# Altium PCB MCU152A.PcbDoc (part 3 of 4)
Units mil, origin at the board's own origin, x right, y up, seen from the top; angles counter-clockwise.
Board outline 2307.9 x 3007.9 mil, 4 copper layers (Top Signal, GND, PWR, Bottom Signal), stack 61.6 mil thick; 198 components, 136 nets, 740 pads, 401 vias.
Unrouted connection lines stored in the file: 147.
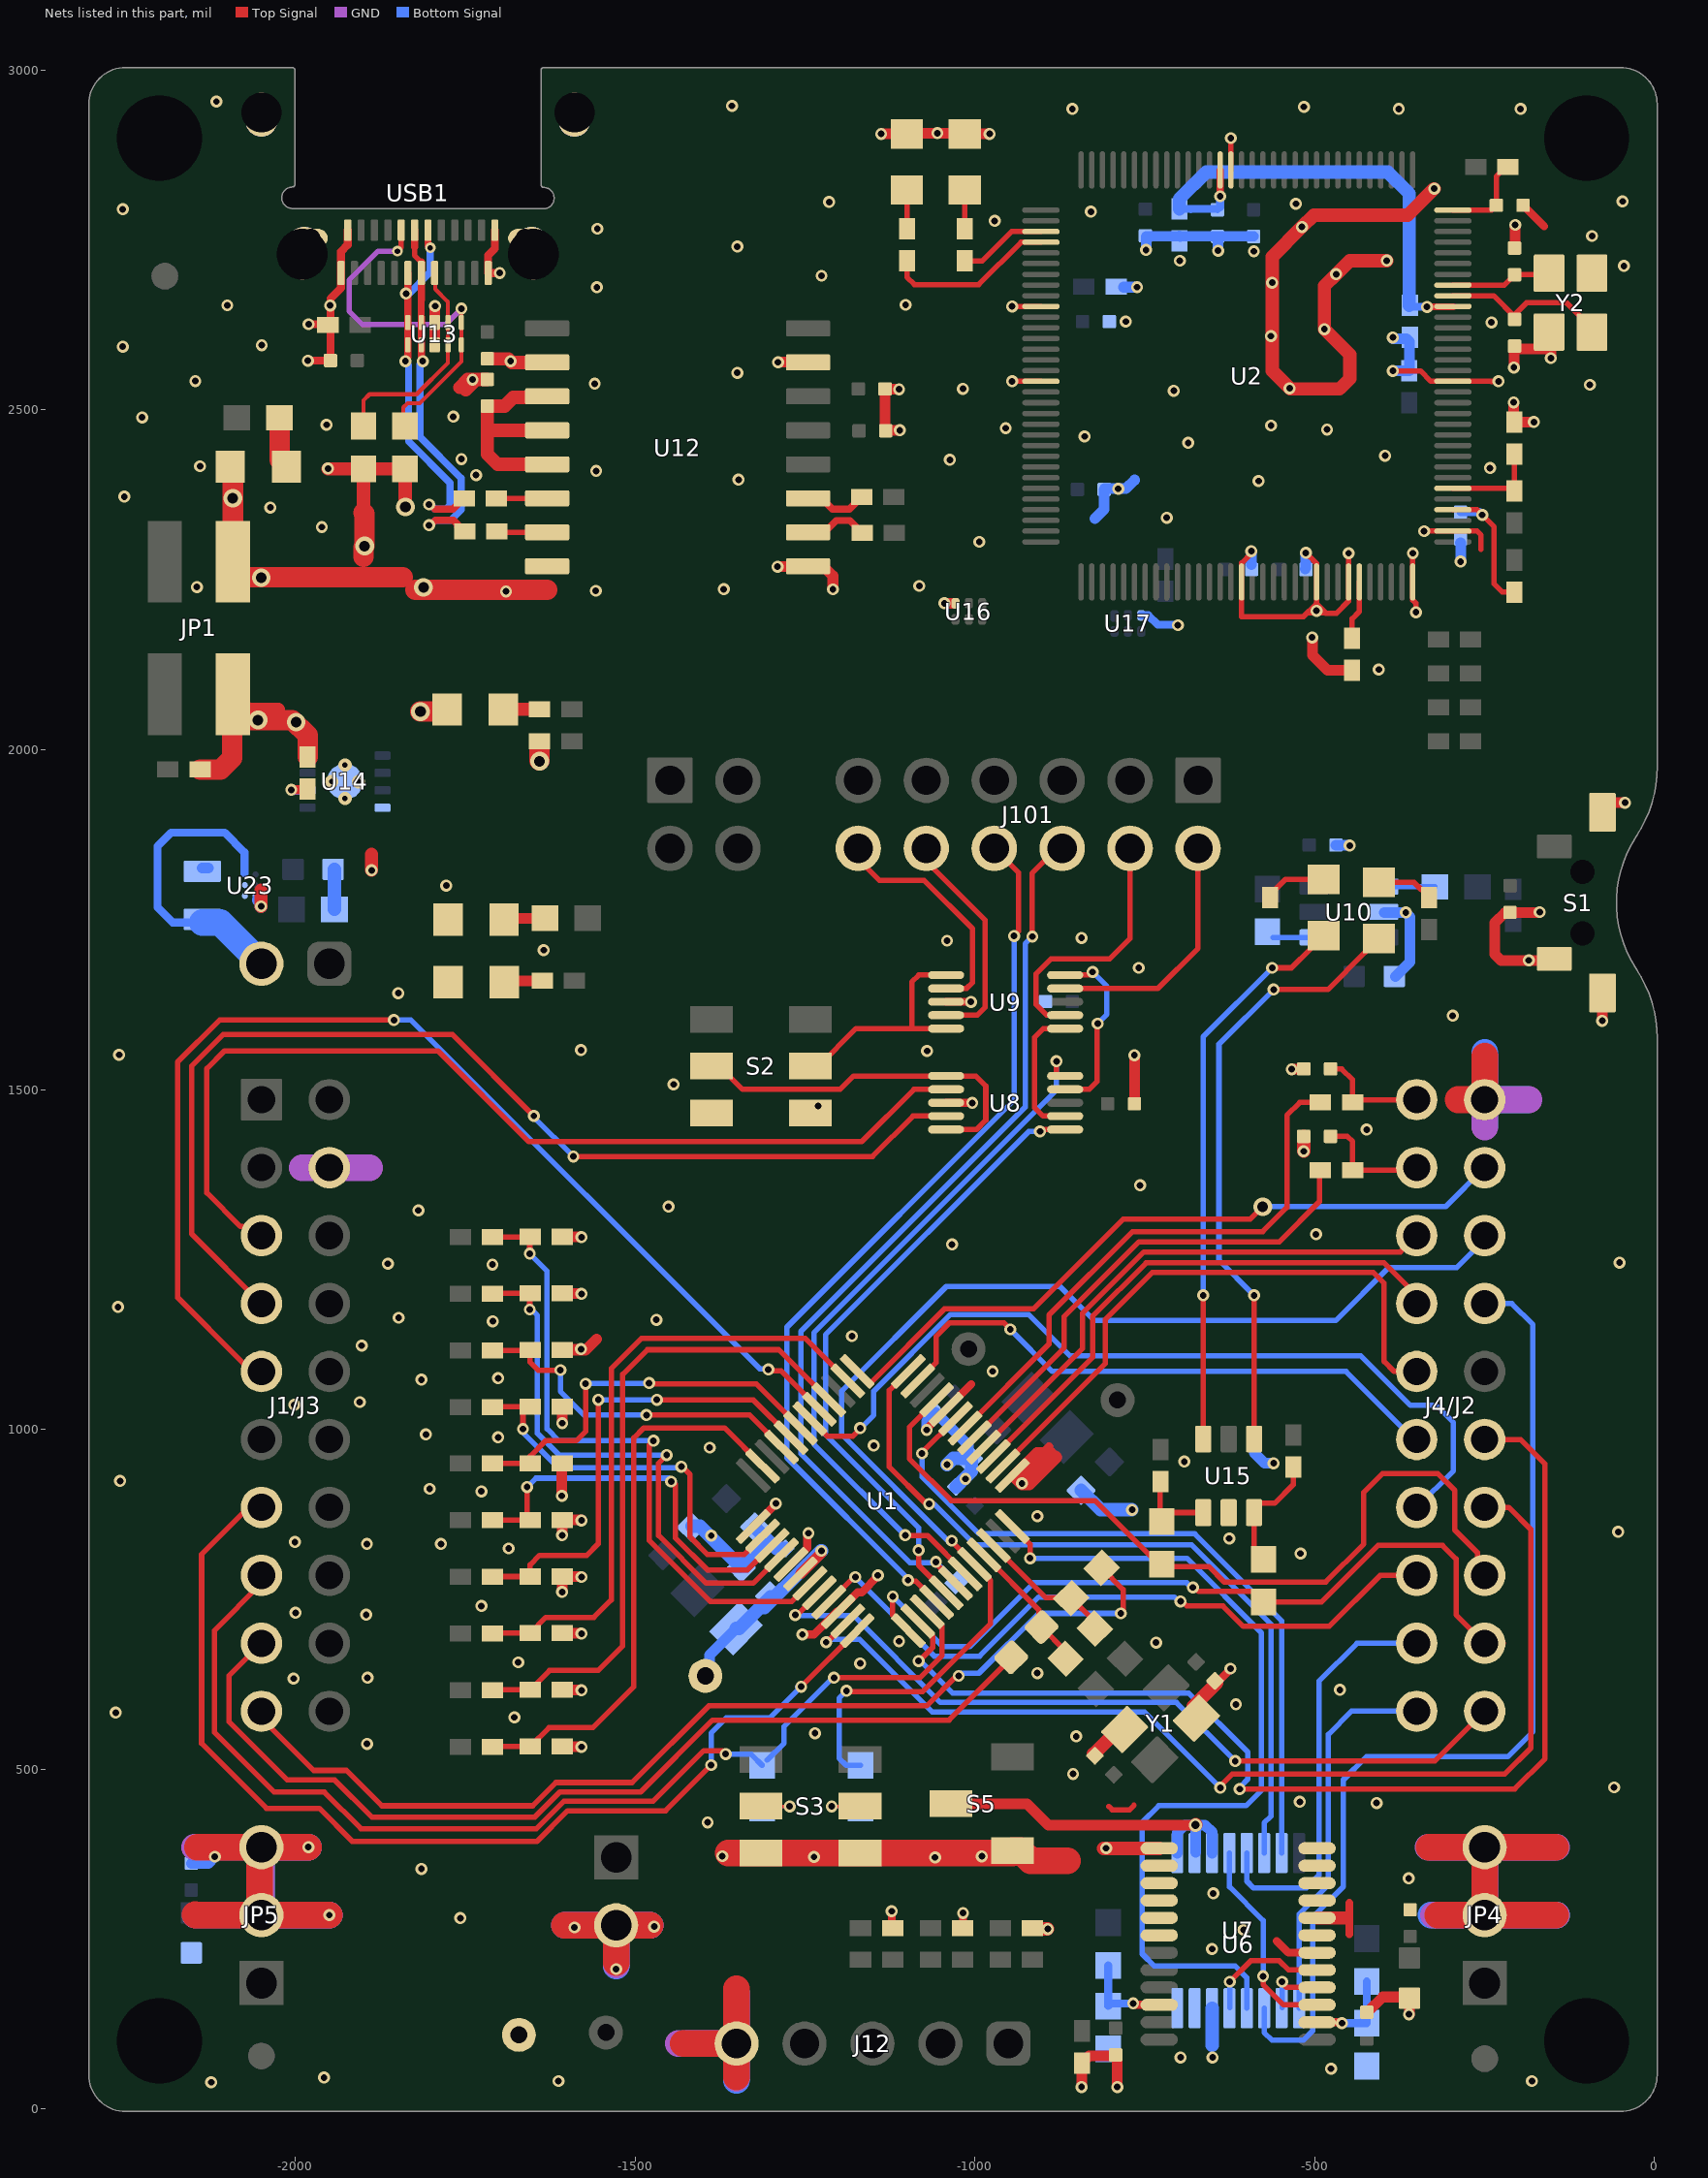
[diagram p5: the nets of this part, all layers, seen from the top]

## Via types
v1: diameter 17.72, hole 9.84, Top Signal to Bottom Signal, tented both sides, 368 vias
v2: diameter 27.56, hole 15.75, Top Signal to Bottom Signal, tented both sides, 21 vias
v3: diameter 19.68, hole 11.81, Top Signal to Bottom Signal, tented both sides, 6 vias
v4: diameter 19.68, hole 7.87, Top Signal to Bottom Signal, tented both sides, 4 vias
v5: diameter 15.75, hole 7.87, Top Signal to Bottom Signal, tented both sides, 2 vias

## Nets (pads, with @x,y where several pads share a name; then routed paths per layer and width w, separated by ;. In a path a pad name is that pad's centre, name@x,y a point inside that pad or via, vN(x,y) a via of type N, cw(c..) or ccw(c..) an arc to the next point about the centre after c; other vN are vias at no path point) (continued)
GND: C1.1 C2.1 C3.2 C4.2 C5.1 C6.2 C7.2 C8.2 C9.2 C10.2 C11.1 C12.2 C13.2 C14.2 C15.2 C17.2 C18.2 C19.2 C20.2 C21.2 C22.2 C23.2 C28.2 C29.2 C30.2 C31.1 C32.1 C34.2 C35.2 C36.2 C37.1 C38.1 C43.2 C45.2 C58.1 C59.1 C62.2 C63.2 C64.2 C65.1 C66.1 C67.1 C68.1 C69.1 C70.1 C71.2 C72.2 C73.1 C74.2 C75.1 C76.2 C77.1 C78.2 C79.2 C80.2 C81.2 C119.2 C120.2 C124.2 C125.1 J1/J3.22 J4/J2.20 J12.5 J15.2 JP1.4 JP4.2 JP4.3 JP5.2 JP5.3 LED0.1 LED1.1 LED2.1 LED3.1 LED6.1 R18.1 R19.2 R75.1 R76.1 S1.1 S1.2 S1.3 S2.3 S2.6 S3.1 S3.4 S5.1 TP6.1 U1.13 U1.17 U1.22 U1.37 U1.44 U2.10 U2.17 U2.48 U2.55 U2.58 U2.64 U2.66 U2.80 U2.114 U6.6 U6.7 U6.8 U6.9 U6.10 U6.11 U6.12 U6.13 U6.14 U6.15 U6.16 U6.17 U6.18 U7.6 U7.7 U7.8 U8.3 U9.3 U10.2 U12.9 U12.15 U14.4 U14.9 U15.2 U16.3 U17.3 U23.A2 Y1.2 Y1.4 Y2.2 Y2.4 | length 11507.1
  Top Signal w7.87: v1(-945.31,2542.13) U2.17@-902.95,2542.13 ; v1(-945.31,2652.36) U2.10@-902.95,2652.36 ; -803,445 -798.11,440.11 -772.47,440.11 -766,446.58 ; U2.114@-623.43,2853.15 v1(-623.43,2900) ; v1(-593.35,2292.32) -593.35,2289.14 -607.68,2274.81 U2.48@-607.68,2246.85 -607.68,2196 -516.51,2196 -497.79,2214.72 ; v1(-513.11,2289.8) -513.11,2289.61 -507.76,2284.25 -507.48,2284.25 -497.44,2274.21 U2.55@-497.44,2246.85 v1(-497.44,2204.49) ; -508.79,2201.72 -486.45,2201.72 ; -497.09,2214.72 -483.37,2201 -467.81,2201 -450.2,2218.62 U2.58@-450.2,2246.85 v1(-450.2,2289.21) ; v1(-385,2557.48) -344.54,2557.48 -329.19,2542.13 U2.80@-296.65,2542.13 -240.1,2542.13 -239.8,2541.83 ; v1(-355.71,2289.21) U2.64@-355.71,2246.85 -355.71,2220.32 -351.02,2215.63 v1(-351.02,2202.32) ; v1(-339.02,2321.65) U2.66@-296.65,2321.65 -261.09,2321.65 -255.18,2315.74 -255.18,2295
  Top Signal w11.81: U1.13@-1326.37,856.84 v1@-1292.68,890.53 ; U1.17@-1270.69,801.17 -1246.67,825.18 -1246.67,845.33 v1(-1245,847) ; v1(-1254,698) -1236.78,698 -1203.22,731.57 U1.22@-1201.09,731.57 -1172.66,760 -1166.57,760 v1@-1142.25,784.32 ; C20.2@-1122.47,267.36 v1(-1122.47,290.68) ; v1(-1071,999) -1071,1000.85 U1.44@-1042.41,1029.44 -1005.53,1066.32 ; U8.3@-1042.51,1480.5 v1@-1004.25,1480.5 ; U9.3@-1042.51,1629 v1(-1006,1629) ; C19.2@-1017.55,266.57 v1(-1017.55,288.19) ; v1@-927.92,926.97 -892.02,962.87 ; -891,974.61 -897.7,967.91 ; -887,967.91 -897.7,967.91 ; C4.2@-644.05,626.87 -623.99,646.92 v1(-623.99,647.76) ; -555.93,247 -538.64,229.7 U6.6@-496.61,229.7 ; -449,257 -449,302.92 ; C65.1@-192.44,2800.24 -162.28,2770.08 ; -897.7,967.91 -909.07,967.91 U1.37@-944.97,932.01 -933.6,932.01 -897.7,967.91
  Top Signal w15.75: v1(-1608,902) -1608,947.25 -1607,948.25 C13.2@-1608,949.25 ; v1(-1607.5,843.96) -1607.38,844.08 C8.2@-1607.38,866.54 v1@-1579,866.54 ; C15.2@-1607.38,533.21 v1@-1579,533.21 ; C23.2@-1607.38,616.54 v1@-1579,616.54 ; C14.2@-1607.38,699.88 v1@-1579,699.88 ; v1@-1607.38,760.74 C9.2@-1607.38,783.21 v1@-1579,783.21 ; v1(-1607.38,1009) C22.2@-1607.38,1033.21 ; C21.2@-1607.38,1199.88 v1@-1579,1199.88 ; C7.2@-1607.38,1283.21 v1@-1579,1283.21 ; v1(-1579.77,1118) -1605.92,1118 C17.2@-1607.38,1116.54 -1572.87,1116.54 -1556.42,1133 ; v1(-1290.55,2269.29) U12.9@-1270.71,2269.29 ; v1(-1289.76,2570.24) U12.15@-1244.41,2570.24 ; U12.9@-1222.68,2269.45 -1209.11,2255.89 -1209,2256 v1(-1209,2236) ; v1(-1138.11,2906.38) LED3.1@-1118.27,2906.38 ; C59.1@-1132.31,2470.39 C58.1@-1132.31,2531 ; C59.1@-1132.05,2470.12 C59.1@-1131.3,2469.37 ; C58.1@-1132.05,2530.45 v1(-1111.68,2530.45) ; C59.1@-1130.51,2470.08 v1(-1110.67,2470.08) ; LED3.1@-1090.2,2907.24 v1(-1055.28,2907.24) LED2.1@-1035.43,2907.24 ; v1@-1044.91,2215.54 U16.3@-1032,2215.54 ; LED2.1@-998.39,2906.18 v1(-978.54,2906.18) ; v1(-843.12,32) C12.2@-843.12,66.45 ; C12.2@-842.19,67.38 -831.91,77.66 -794.65,77.66 C11.1@-793,79.32 ; v1(-790.5,32) C11.1@-790.5,76.82 ; C45.2@-765.32,1479 v1@-765.32,1550.5 ; v1(-533.93,1529.82) -533.49,1530.25 C2.1@-516.21,1530.25 ; v1@-503,2165 -503,2139 -480.93,2116.93 R76.1@-445,2116.93 ; C10.2@-422.59,142.04 -422.59,142.95 -421.53,144.01 -420.63,144.01 -400.14,164.49 -360.68,164.49 v1@-360.68,138.97 ; R75.1@-207.32,2491.34 v1(-207.32,2511.18) ; v1(-206.93,2562.6) -206.93,2582.44 ; C79.2@-205.98,2590 Y2.4@-158.74,2590 ; C78.2@-205.98,2738.31 -205.34,2738.95 -205.34,2772.03 v1(-204.96,2772.4) -204.96,2752.56 ; R75.1@-197.32,2482.24 v1(-177.48,2482.24) ; v1@-168.6,1760.6 C38.1@-212.72,1760.6 -219.81,1760.6 -235.17,1745.25 -235.17,1699.1 -226.1,1690.02 v1(-185,1690.02) -149.86,1690.02 S1.3@-147.56,1692.32 ; v1(-152.64,2576.26) Y2.4@-152.64,2596.1 ; v1(-77,1601) S1.1@-77,1641.82 ; S1.2@-62.57,1922 v1(-43.5,1922)
  Top Signal w19.68: JP1.4@-2076.12,2043.64 -2093,2060.53 -2103,2070.53 JP1.4@-2091.97,2081.56 -2069.47,2059.06 -2025.47,2059.06 ; v1(-2050.5,1769.62) -2050.5,1793.11 ; v1(-1887.89,1822.62) -1887.89,1846.11 ; U1.37@-941.25,930.62 v1(-930.91,920.27) -920.27,920.27 -882,958.54 ; C18.2@-914,264.62 v1(-893,264.62) ; C3.2@-826.07,522.34 -824.85,522.34 -789.06,558.13 Y1.4@-779.89,558.13 ; v1@-810.58,383.25 U6.13@-728.89,383.25 ; Y1.2@-678.75,592.16 C4.2@-644.05,626.87 ; v1(-516.32,1409) C1.1@-516.32,1430.89 ; U6.8@-496.61,280.89 -454,280.89 ; v1(-394.09,2719.68) -448.58,2719.68 v1(-468.5,2699.76) -485.83,2682.44 v1(-485.83,2618.8) -448.58,2581.56 -448.58,2545.92 -463.59,2530.91 -536.02,2530.91 v1(-537.01,2531.89) -562.6,2557.48 v1(-562.6,2687.4) -562.6,2725.43 v1(-518.74,2769.29) -501.42,2786.61 -363.19,2786.61 v1(-324.21,2825.59) ; Y2.2@-95,2704.09 Y2.2@-92.13,2701.22 Y2.2@-91.91,2701
  Top Signal w30: C62.2@-2140.38,1971 -2110,1971 -2093,1988 -2093,2060.53 JP1.4@-2093,2071 ; JP1.4@-2080.59,2043.64 -2076.12,2043.64 v2(-2055,2043.64) -2004.64,2043.64 -1982.12,2021.12 C63.2@-1982.12,1989.42 ; v2(-1816,2056) LED0.1@-1780.21,2056 ; v2@-1640.59,1984.25 C64.2@-1640.59,2007
  Top Signal w39.37: -2147.75,285.56 -2147.19,285 JP5.2@-2053,285 ; -2143.75,385 -2053,385 JP5.2@-2053,285 ; JP5.2@-2053,276.18 JP5.2@-2053,285 ; JP5.3@-2050,385 v1(-1981,385) ; v1(-1950,285) JP5.2@-2050,285 JP5.2@-2053,285 ; -1604,270 J15.2@-1528,270 ; -1528,215 J15.2@-1528,270 ; v1@-1478,270 J15.2@-1528,270 ; -1429.02,95.98 J12.5@-1350.8,95.98 ; -1350.8,46.78 J12.5@-1350.8,95.98 ; -1350.8,176.67 J12.5@-1350.8,95.98 ; S3.4@-1314.87,376.25 -1363,376.25 ; v1@-1236.85,376.25 -1363,376.25 ; S5.1@-944.72,376.25 -1363,376.25 ; S5.1@-944.72,380.1 -932.91,380.1 -918.01,365.2 -864.16,365.2 ; -332,385 JP4.3@-250,385 ; -319,285 JP4.2@-250,285 ; -289.23,1485 J4/J2.20@-250,1485 -250,1549 ; -146,285 JP4.2@-250,285 ; -146,385 JP4.3@-250,385 ; JP4.2@-250,285 JP4.3@-250,385
  GND w39.37: -2148.25,385.06 -2148.19,385 JP5.3@-2050,385 ; -2147.25,285.06 -2147.19,285 JP5.2@-2050,285 ; -1989.76,1385 J1/J3.22@-1950,1385 -1891,1385 ; v1(-1981,385) JP5.3@-2050,385 ; v1(-1950,285) JP5.2@-2050,285 ; -1602,270 J15.2@-1528,270 ; v1@-1528,211.56 J15.2@-1528,270 ; v1@-1478,270 J15.2@-1528,270 ; -1436.68,95.98 J12.5@-1350.8,95.98 ; -1350.8,44.8 J12.5@-1350.8,95.98 ; -1350.8,168.7 J12.5@-1350.8,95.98 ; -333,385 JP4.3@-250,385 ; -325,285 JP4.2@-250,285 ; -250,1444.77 J4/J2.20@-250,1485 ; -250,1549.19 J4/J2.20@-250,1485 ; -185,1485 J4/J2.20@-250,1485 ; -144,285 JP4.2@-250,285 ; -144,385 JP4.3@-250,385 ; JP5.2@-2050,285 JP5.3@-2050,385 ; JP4.2@-250,285 JP4.3@-250,385
  Bottom Signal w11.81: U17.3@-755.32,2197.81 -744.81,2197.81 -731,2184 v1@-701.67,2184
  Bottom Signal w15: C67.1@-748.23,2755.24 -747.7,2755.77 -698.72,2755.77 -590.45,2755.77 C66.1@-590,2755.32
  Bottom Signal w15.75: C81.2@-2153.25,361.25 -2128.25,361.25 v1(-2118.5,371) ; v1(-1071,999) -1071,1012 C32.1@-1057.92,1025.08 -1009.61,976.77 C30.2@-1009.61,957.12 ; -823.23,2340.16 -809.88,2353.5 C70.1@-809.88,2383.11 ; C70.1@-808.9,2384.09 v1(-789.05,2384.09) -778.11,2384.09 -765.35,2396.85 ; C72.2@-781.38,2680.75 v1(-761.54,2680.75) ; v1(-748.23,2735.39) C67.1@-748.23,2755.24 ; C76.2@-699.17,2756.22 -698.72,2755.77 C76.2@-698.04,2755.09 ; v1(-642.17,2734.41) C75.1@-642.17,2754.25 ; C69.1@-593.35,2272.48 v1(-593.35,2292.32) ; C5.1@-588.58,981.45 -588.58,965 -573.61,950.03 v1(-560.5,950.03) ; C68.1@-514.02,2266.26 -513.11,2267.17 v1(-513.11,2289.8) ; C124.2@-468.77,1859.72 v1@-449.3,1859.72 ; U10.2@-397.74,1760.6 v1(-366,1760.6) -366,1760.07 -359.96,1754.03 -359.96,1687.54 C125.1@-381.06,1666.45 ; v1(-385,2557.48) C71.2@-365.16,2557.48 ; v1@-385,2604.76 -365.16,2604.76 -360.79,2600.39 C71.2@-360.79,2557.76 ; C77.1@-285.47,2304.76 -285.39,2304.68 v1(-285.39,2276.86)
  Bottom Signal w19.68: -2053.8,1778.92 -2050.5,1775.62 v1(-2050.5,1769.62) ; C119.2@-1942.5,1765 C120.2@-1942.5,1824 ; C35.2@-1416.05,857.27 -1404.71,857.27 -1345.18,797.75 -1307.6,835.34 ; C6.2@-1322.62,854.73 -1292.46,824.57 C37.1@-1278.81,824.57 ; v1(-1041,948) -1031.88,957.12 C30.2@-1009.61,957.12 ; C31.1@-1027.92,915.26 -1005,938.18 C30.2@-1005,954 ; C29.2@-843.88,910.12 -815.24,881.48 v1(-768.83,881.48) ; -651.14,93.38 U7.6@-651.14,148.01
  Bottom Signal w39.37: v1(-1981,385) JP5.3@-2050,385 JP5.2@-2050,285 v1(-1950,285) ; -1604,270 J15.2@-1528,270 ; v1@-1528,210.06 J15.2@-1528,270 ; v1@-1478,270 J15.2@-1528,270 ; -1422.11,95.98 J12.5@-1350.8,95.98 ; -1350.8,42.2 J12.5@-1350.8,95.98 ; -1350.8,171.05 J12.5@-1350.8,95.98 ; -328.85,285 JP4.2@-250,285 ; -328.85,385 JP4.3@-250,385 ; -250,1446.84 J4/J2.20@-250,1485 ; -250,1554.26 J4/J2.20@-250,1485 ; -187.75,1485 J4/J2.20@-250,1485 ; -148.5,385 JP4.3@-250,385 ; -144,285 JP4.2@-250,285 ; JP4.2@-250,285 JP4.3@-250,385
  other v1: -2124,39 -1613,40.74 -180.5,40.74 -1957.94,46 -476.1,59 -697.5,75.54 -650.47,75.54 -361.41,138.97 -1527.99,205.56 -651.18,235.06 -604.7,263.32 -1589.37,266.85 -1472,268 -1757.36,280.5 -649.37,317 -361.7,338.97 -1814.6,353 -1058.8,369.93 -1236.85,370.67 -1371.85,371.67 -990,371.5 -807,383.5 -1393.42,421.5 -409.07,450 -521.94,451.82 -59.5,473 -855.68,492.82 -1579,532.53 -1894.69,536.97 -851,548.03 -1235.46,552.59 -1677.69,575.97 -2264.5,583 -616,595 -1579,615.86 -462.94,616.5 -2002.69,633.15 -1893.89,634.31 -908.27,641.07 -1169,655.38 -1672.2,656.97 -733.49,686.11 -1111.68,688 -1579,699.2 -1895.89,727.03 -1999.69,729.97 -1726.26,739.87 -1607.5,760.62 -1579,782.53 -1142.86,784.93 -521,817.16 -1686.21,824.61 -1894.78,831.09 -1785.94,831.09 -2000.69,833.97 -625.71,839.19 -1388,843.47 -53.48,849 -1579,865.86 -908.27,872 -1293,890.85 -1726.31,908.54 -1802.47,912.32 -2258,924 -1014,927 -692,952.53 -1390.33,972.93 -1149,976 -1701.61,988 -1808,992.3 -2001.69,1035.97 -1905.21,1039.97 -1814.6,1073.02 -1701.61,1075.15 -974,1085.26 -1902.5,1123 -1181,1137 -1709.59,1158.96 -1468.92,1160.94 -1848,1164.1 -2261,1180 -1579,1199.2 -1710.01,1242.31 -1863.89,1243.62 -51.5,1245.17 -1033.85,1272 -1579,1282.53 -498.03,1287 -1818.94,1322 -1451,1327.5 -757,1359 -423.7,1441.06 -1231,1476 -1004,1480.25 -1443.41,1507.5 -2259.5,1551 -765.35,1550.5 -1070.5,1556.72 -1579.77,1558 -297,1608.52 -1848.66,1641.85 -758.94,1679.04 -1634.72,1705 -1041.02,1718.94 -843.14,1723 -169,1761 -1777.94,1800.11 -448.58,1859 -405.66,2117.97 -503.93,2165.32 -701.37,2183.32 -1045,2215.63 -1369.76,2236.22 -1082,2241 -993.7,2305.91 -717.91,2341.5 -582.6,2395.43 -1347.87,2397.4 -242.14,2414.51 -1037.01,2426.73 -396.46,2432.68 -686.22,2451.57 -838.58,2461.02 -481.89,2471.26 -954.72,2473.23 -564.29,2477.05 -707.48,2528.35 -1017.76,2531.22 -95.26,2537 -229.61,2542.13 -1349.8,2554.57 -385,2606.65 -564.57,2608.62 -239.96,2628.74 -777.95,2630.05 -1102,2654.68 -1225.79,2697.52 -45,2712 -698.52,2719.56 -589.56,2733.48 -1349.8,2740.51 -92,2756 -971.06,2778.35 -829.41,2791.81 -527.83,2803.35 -1214.49,2806.11 -47,2807 -856.77,2942.99 -376.38,2942.99 -197.09,2942.99 -516,2946 -1357.48,2947.52
  other v2: -1640.59,1983 -1999,2040.64
  other v4: -1927,1928.39 -1946.68,1953 -1907.32,1953 -1927,1977.61
GPIO0: R1.1 U1.42 | length 826
  Top Signal w7.87: U1.42@-1014.57,1001.6 -891,1125.18 -891,1168 -768,1291 -576.5,1291 -541,1326.5 -541,1462 -522,1481 R1.1@-491.62,1481
GPIO1: R2.1 U1.41 | length 725.2
  Top Signal w7.87: U1.41@-1000.65,987.69 -869,1119.34 -869,1165.61 -758.61,1276 -551.91,1276 -493,1334.91 -493,1379.62 R2.1@-491.62,1381
GPIO2: J4/J2.38 U1.40 | length 796.1
  Top Signal w7.87: U1.40@-986.73,973.77 -841.48,1119.02 -841.48,1171 -751.49,1261 -374,1261 J4/J2.38@-350,1285
GPIO3: J4/J2.37 U1.39 | length 808
  Top Signal w7.87: U1.39@-972.81,959.85 -827,1105.66 -827,1166 -748.22,1244.78 -397.78,1244.78 -350,1197 J4/J2.37@-350,1185
GPIO4: J4/J2.36 U1.38 | length 892.9
  Top Signal w7.87: U1.38@-958.89,945.93 -808,1096.82 -808,1161.75 -738.75,1231 -414,1231 -398,1215 -398,1099.89 -383.11,1085 J4/J2.36@-350,1085
GPIO5: J4/J2.35 U1.47 | length 863.5
  Top Signal w7.87: U1.47@-1084.17,1071.2 -1057,1098.37 -1057,1136.81 -1037.12,1156.69 -957.53,1156.69 -950.74,1149.89 v1@-946.47,1149.89
  Bottom Signal w7.87: v1(-948,1147) -886,1085 -454,1085 -354,985 J4/J2.35@-350,985
GPIO6: U1.48 U7.14 | length 1154.7
  Top Signal w7.87: U1.48@-1098.09,1085.12 -1126,1057.21 -1126,944.51 -1073.49,892 v1@-1063,892
  Bottom Signal w7.87: v1(-1067.5,890) -1062,890 -1061.15,890.85 -1000.43,830.14 -681.45,830.14 -564.57,713.25 -564.57,430.43 -574.36,420.64 U7.14@-574.36,376.36
GPIO6_BP: J4/J2.32 U7.13 | length 611.9
  Bottom Signal w7.87: U7.13@-599.96,376.36 -599.96,334.96 -590,325 -512.44,325 -493.78,343.66 -493.78,629.22 -438,685 J4/J2.32@-350,685
GPIO6_Q1A: U6.3 U7.12 | length 305.7
  Top Signal w7.87: v1(-576,195) -576,183 -545.93,152.93 U6.3@-496.61,152.93
  Bottom Signal w7.87: U7.12@-625.55,376.36 -625.55,326.55 -576,277 v1(-576,195)
GPIO7: U1.43 U7.15 | length 1064.7
  Top Signal w7.87: v1(-1077.87,964.41) -1077.87,965.68 -1028.49,1015.06 U1.43@-1028.49,1015.52
  Bottom Signal w7.87: v1(-1077.87,964.41) -1077.87,929.87 -994,846 -676.62,846 -548.77,718.16 U7.15@-548.77,376.36
GPIO7_BP: J4/J2.31 U7.1 | length 565
  Bottom Signal w7.87: U7.1@-523.18,148.01 -523.18,286.38 -480,329.56 -480,551 -446,585 J4/J2.31@-350,585
GPIO7_Q1B: U6.4 U7.2 | length 95.4
  Top Signal w7.87: v1(-548,187) -548,185 -541.52,178.52 U6.4@-496.61,178.52
  Bottom Signal w5: U7.2@-548.77,148.01 U7.2@-548,148.79
  Bottom Signal w7.87: U7.2@-548,148.79 v1(-548,187)
GPIO12: J1/J3.7 U1.24 | length 1580.6
  Top Signal w7.87: J1/J3.7@-2050,885 -2069,885 -2138,816 -2138,537.56 -2042.44,442 -1964.75,442 -1916.19,393.44 -1644.5,393.44 -1599.4,438.54 -1455.43,438.54 v1(-1388.21,505.76) ; v1(-1255.75,621.24) U1.24@-1173.25,703.73
  Bottom Signal w7.87: v1(-1388.21,505.76) -1388.21,552.79 -1366,575 -1301.98,575 v1(-1255.75,621.24) v1@-1260.76,621.24
GPIO13: J4/J2.14 U1.23 | length 1605.8
  Top Signal w7.87: v1(-1219,686.55) -1215.37,686.55 -1216.82,688 U1.23@-1187.17,717.65 ; v1(-639,472.37) -639,475 -621.18,492.82 -220.18,492.82 -182,531 -182,852.5 -214.5,885 J4/J2.14@-250,885
  Bottom Signal w7.87: v1(-1219,686.55) -1214.55,691 -1169.98,691 -1062.98,584 -750.63,584 v1(-639,472.37)
GPIO16: J4/J2.15 U1.26 | length 1683.4
  Top Signal w7.87: U1.26@-1084.17,717.65 -1062.28,695.76 -1062.28,678.72 -1082.95,658.05 -1083,658.09 v1(-1083,659) ; v1(-610.56,470.52) -205.84,470.52 -161,515.35 -161,948.88 -197.12,985 J4/J2.15@-250,985
  Bottom Signal w7.87: v1(-1083,659) -1080,659 -1033,612 -685.6,612 -598.3,524.7 -598.3,485.44 -610.56,473.18 v1(-610.56,470.52)
GPIO18_BP: J1/J3.9 R12.1 | length 1442
  Top Signal w8: J1/J3.9@-2050,685 -2097.5,637.5 -2097.5,569.5 -2011.92,483.92 -1942.19,483.92 -1887.56,429.29 -1647.72,429.29 -1610.84,466.16 -1491.84,466.16 -1386,572 -1038,572 -946.56,663.44 R12.1@-946.56,664.28
GPIO18_X2: R10.1 R12.2 U1.33 | length 181.5
  Top Signal w8: U1.33@-986.73,815.08 -906.02,734.37 R12.2@-906.02,717 ; R12.2@-902.02,708.83 R10.1@-866.65,673.45
GPIO19_BP: J1/J3.10 R13.1 | length 1523.7
  Top Signal w8: J1/J3.10@-2050,585 -2050,575 -1973,498 -1924.84,498 -1872.67,445.83 -1650.84,445.83 -1616.6,480.07 -1504.58,480.07 -1391.63,593.02 -1070.99,593.02 v1@-1025.01,639.01 ; R13.1@-813.79,796.01 -781.93,764.14 v1@-781.93,728
  Bottom Signal w8: v1@-1023,641 -994.32,641 -906.32,729 v1(-785.43,729)
  other v1: -1024,637
GPIO19_X1: R11.1 R13.2 U1.34 | length 190.7
  Top Signal w8: U1.34@-972.81,829 -895.81,752 R13.2@-863.04,752 ; R13.2@-858.34,751.47 R11.1@-823.63,716.76
GPIO24: J1/J3.8 R15.1 U1.27 | length 1592.4
  Top Signal w7.87: J1/J3.8@-2050,785 -2050,773 -2119,704 -2119,553.69 -2031.25,465.94 -1957.3,465.94 -1903.51,412.16 -1645.27,412.16 -1605.11,452.32 -1473.68,452.32 -1399,527 -1371.74,527 v1(-1366.85,522.11) ; v1@-1209.29,634.31 v1(-1207.5,634.31) -1081.24,634.31 -1048.5,667.05 -1048.5,709.82 U1.27@-1070.25,731.57
  Bottom Signal w7.87: v1@-1364.85,520.11 v1(-1366.85,522.11) R15.1@-1329.85,522.11 ; R15.1@-1327.85,520.11 -1313.17,505.43 R15.1@-1313.08,505.43 R15.1@-1313.08,505.89 ; R15.1@-1306,513 -1281,538 -1281,562.6 -1209.29,634.31 v1(-1207.5,634.31)
GPIO29: J4/J2.19 U1.1 | length 1060.4
  Top Signal w7.87: U1.1@-1173.25,1085.12 -1157.59,1069.46 -1152.54,1069.46 -1045,1177 -913.93,1177 -781.93,1309 -595,1309 v2(-576.5,1327.5)
  Bottom Signal w7.87: v2(-576.5,1327.5) -307.5,1327.5 J4/J2.19@-250,1385
GPIO32: J4/J2.18 R16.2 U1.32 | length 1917.5
  Top Signal w7.87: v1@-1189,614 -1077,614 -977,714 -977,777.51 U1.32@-1000.65,801.17 -1035.49,836 v1(-1034,836)
  Bottom Signal w7.87: v1(-1189,615) -1200,604 -1200,516 -1189.43,505.43 R16.2@-1168.35,505.43 ; v1(-1034,836) -1040,836 -1196,992 -1196,1056.23 -1042.15,1210.08 -874.7,1210.08 -824.44,1159.83 -469.17,1159.83 -391,1238 -291,1238 -250,1279 J4/J2.18@-250,1285
GPIO33: J4/J2.12 R9.1 U1.25 | length 1192.1
  Top Signal w7.87: v1(-1121,753.9) -1121,726.64 U1.25@-1098.09,703.73 ; v1(-679.29,767.24) -676.63,767.24 -670.61,761.22 -589.94,761.22 -577,748.28 R9.1@-577,741 ; R9.1@-572.67,743.21 R9.1@-575.17,745.72 -490.28,745.72 -407,829 -312,829 -292,809 -292,727 J4/J2.12@-250,685 ; J4/J2.12@-250,681.97 J4/J2.12@-250,685 ; J4/J2.12@-223,685 J4/J2.12@-250,685
  Bottom Signal w7.87: v1(-1121,753.9) -1047.1,680 -1007.68,680 -913.68,774 -688.72,774 -681.96,767.24 v1(-679.29,767.24)
GPIO35: U1.31 U8.10 | length 1046.6
  Top Signal w7.87: v1@-1102.79,843.79 -1069.98,843.79 -1014.57,788.38 U1.31@-1014.57,787.25 ; v1(-880,1541.52) -880,1522 -877.87,1519.87 U8.10@-867.32,1519.87
  Bottom Signal w7.87: v1@-1102.79,843.79 -1237.03,978.03 -1237.03,1141.97 -880,1499 v1(-880,1541.52)
  other v1: -1102.5,844.08
GPIO35/37_SEL1: S2.2 U8.1 U8.5 | length 546.4
  Top Signal w7.87: S2.2@-1387.69,1534.31 -1375.88,1534.31 -1341.76,1500.19 -1198.4,1500.19 -1178.71,1519.87 U8.1@-1042.51,1519.87 -998.87,1519.87 -984,1505 -984,1455 -997.87,1441.13 U8.5@-1042.51,1441.13
GPIO35/37_SEL2: S2.5 U9.1 U9.5 | length 345.5
  Top Signal w7.87: S2.5@-1242.02,1534.31 -1230.21,1534.31 -1174.89,1589.63 -1092.83,1589.63 ; U9.5@-1042.51,1589.63 -1092.83,1589.63 ; U9.1@-1042.51,1668.37 -1082.63,1668.37 -1092.83,1658.17 -1092.83,1589.63
GPIO35_BP: J1/J3.3 U8.2 | length 1475.2
  Top Signal w7.87: J1/J3.3@-2050,1285 -2064.38,1285 -2077.64,1298.25 -2080.85,1298.25 -2130.38,1347.78 -2130.38,1530.66 -2104.31,1556.72 -1789.95,1556.72 -1656.29,1423.07 -1166.93,1423.07 -1089.81,1500.19 U8.2@-1042.51,1500.19
GPIO35_XDS: U8.9 U9.10 | length 270
  Top Signal w7.87: U8.9@-867.32,1500.19 -831.81,1500.19 -820,1512 v1@-820,1597 ; U9.10@-867.32,1668.37 -831.63,1668.37 v1(-827,1673)
  Bottom Signal w7.87: v1(-827,1673) -805.72,1651.72 -805.72,1610.79 v1(-819.51,1597)
GPIO37: U1.29 U8.6 | length 931.7
  Top Signal w7.87: v1(-1083,822) -1083,800 U1.29@-1042.41,759.41 ; v1@-905,1438.5 -902.37,1441.13 U8.6@-867.32,1441.13
  Bottom Signal w7.87: v1(-1083,822) -1083,855 -1220.03,992.03 -1220.03,1138.97 -920.72,1438.28 v1(-904.26,1438.28)
GPIO37_BP: J1/J3.4 U8.4 | length 1621.5
  Top Signal w7.87: J1/J3.4@-2050,1185 -2152.83,1287.83 -2152.83,1534.31 -2106.14,1581 -1769.03,1581 v1(-1649.14,1461.11) ; v1(-1590.92,1401.36) -1150.64,1401.36 -1091.18,1460.82 U8.4@-1042.51,1460.82
  Bottom Signal w7.87: v1(-1649.14,1461.11) -1649.14,1459.59 v1(-1590.92,1401.36)
GPIO37_XDS: U8.7 U9.6 | length 203.6
  Top Signal w7.87: U8.7@-867.32,1460.82 -899.82,1460.82 -912,1473 -912,1577 -899.37,1589.63 U9.6@-867.32,1589.63
GPIO43: U1.36 U7.4 | length 1277.4
  Top Signal w7.87: U1.36@-944.97,856.84 -919,830.87 v1(-919,810.1) v1@-919,810
  Bottom Signal w7.87: v1(-919,810.1) -688.34,810.1 -578.35,700.1 -578.35,468.71 -601.06,446 -729.5,446 -754,421.5 -754,228 -736,210 -617,210 -599.96,192.96 U7.4@-599.96,148.01
GPIO43_BP: J4/J2.17 U7.3 | length 1496.9
  Bottom Signal w7.87: U7.3@-574.36,148.01 -574.36,112.36 -562.75,100.75 -516.85,100.75 -503,114.6 -503,282 -458,327 -458,484 -424,518 -216,518 -179,555 -179,1154 -210,1185 J4/J2.17@-250,1185
GPIO43_Q1I: U6.5 U7.5 | length 185.4
  Top Signal w7.87: v1(-625,187) -594,218 -552.42,218 -538.53,204.11 U6.5@-496.61,204.11
  Bottom Signal w7.87: U7.5@-625,148.56 v1(-625,187)
GPIO45: J4/J2.13 R8.1 U1.45 | length 1251.7
  Top Signal w7.87: U1.45@-1056.33,1043.36 -1096.57,1003.12 -1096.57,956.66 -1034.91,895 -823.64,895 -726.72,798.08 -656.08,798.08 -633,775 -598.19,775 -597.95,775.24 -483.76,775.24 -428,831 -428,907 -400,935 -319,935 -294,910 -294,852 -260.5,818.5 J4/J2.13@-260.5,774.5
GPIO224: J4/J2.34 U1.6 | length 1270.9
  Top Signal w7.87: U1.6@-1242.85,1015.52 -1217.33,990 -1179.6,990 v1@-1168,1001.6 ; v1(-1169,1001.6) v1@-1168,1001.6 ; v1@-1164.6,1001.6 v1@-1168,1001.6
  Bottom Signal w7.87: v1@-1168.8,1000.92 -1149,1020.71 -1149,1056 -1036,1169 -921,1169 -860,1108 -432,1108 -359,1035 -321,1035 -296,1010 -296,939 J4/J2.34@-350,885
GPIO227: J4/J2.11 U1.20 | length 1184.5
  Top Signal w7.87: v1@-1264.34,724 U1.20@-1228.93,759.41 ; v1(-617,511.56) -323.44,511.56 J4/J2.11@-250,585
  Bottom Signal w7.87: v1@-1264.34,724 -1262.34,726 -1179,726 -1051,598 -703.44,598 v1(-617,511.56)
  other v1: -1264.5,726.64
GPIO230: J4/J2.33 U1.21 | length 1006.4
  Top Signal w7.87: U1.21@-1215.01,745.49 -1177.97,782.53 v1(-1176,782.53) ; v1(-697.5,746.56) -694.84,746.56 -688.24,739.96 -635.22,739.96 -605.07,709.82 -478.75,709.82 -403.57,785 J4/J2.33@-350,785
  Bottom Signal w7.87: v1@-1171,777 -1060,666 -993.09,666 -906.09,753 -706.6,753 -700.16,746.56 v1(-697.5,746.56)
GPIO242: J1/J3.5 U1.5 | length 1722.2
  Top Signal w7.87: J1/J3.5@-2050,1085 -2064.38,1085 -2079.18,1099.8 -2079.3,1099.8 -2173.31,1193.81 -2173.31,1540.4 -2111.45,1602.25 v1(-1855,1602.25) ; v1(-1304,1088) -1302.12,1086.12 -1285.6,1086.12 U1.5@-1228.93,1029.44
  Bottom Signal w7.87: v1(-1855,1602.25) -1830.1,1602.25 -1316.67,1088.82 -1304.82,1088.82 v1(-1304,1088)
MCU_A0/CMPDAC/PGA1_INM2: C15.1 R6.2 U1.11 | length 829.1
  Top Signal w7.87: R6.2@-1709.59,533.21 C15.1@-1654.62,533.21 -1626.83,561 -1562.12,561 -1501.88,621.24 -1501.88,987.36 -1487.19,1002.05 -1368.57,1002.05 U1.11@-1312.45,945.93
MCU_A4/PGA1_INM1: C7.1 R21.2 U1.19 | length 946.7
  Top Signal w7.87: R21.2@-1710.01,1282.79 C7.1@-1655.04,1282.79 ; v1(-1655.14,1258.36) -1655.14,1282.69 C7.1@-1655.04,1282.79 ; C7.1@-1654.62,1283.21 C7.1@-1655.04,1282.79 ; v1(-1473,983.05) -1479.48,976.57 -1479.48,836.48 -1389.25,746.25 -1269.93,746.25 U1.19@-1242.85,773.33
  Bottom Signal w7.87: v1(-1655.14,1258.36) -1629.49,1232.71 -1629.49,1000.49 -1612.05,983.05 v1(-1473,983.05)
MCU_A5: C17.1 R22.2 U1.9 | length 515.1
  Top Signal w7.87: R22.2@-1710.01,1116.12 -1655.04,1116.12 C17.1@-1654.62,1116.54 -1654.62,1098.62 -1643,1087 v1(-1610,1087) ; v1@-1484,1018 -1481.21,1020.79 -1331.64,1020.79 U1.9@-1284.61,973.77
  Bottom Signal w7.87: v1(-1610,1087) -1610,1055.67 -1575.33,1021 v1(-1483.5,1021)
MCU_A7: C8.1 R23.2 U1.15 | length 581.6
  Top Signal w7.87: R23.2@-1710.01,866.12 -1655.04,866.12 C8.1@-1654.62,866.54 -1659,870.92 v1(-1659,915) ; v1@-1441,919 -1441,840.26 -1393.74,793 -1334.53,793 U1.15@-1298.53,829
  Bottom Signal w7.87: v1(-1659,915) -1646,928 -1451,928 -1447,924 v1(-1447,923)
MCU_A8/PGA1_OUT: C21.1 R27.2 U1.16 | length 824.3
  Top Signal w7.87: R27.2@-1710.01,1199.46 -1709.59,1199.88 C21.1@-1654.62,1199.88 -1655.14,1199.36 v1(-1655.14,1176.17) ; v1(-1453.65,962.03) -1465.7,949.98 -1465.7,843.7 -1395.25,773.25 -1326.44,773.25 U1.16@-1284.61,815.08
  Bottom Signal w7.87: v1@-1656,1179.38 -1644,1167.38 -1644,994 -1612.03,962.03 v1(-1453.65,962.03)
MCU_A11/PGA1_INP1: C9.1 R28.2 U1.8 | length 703.9
  Top Signal w7.87: R28.2@-1709.59,783.21 C9.1@-1654.62,783.21 -1654.62,800.61 -1640.72,814.51 -1571.26,814.51 -1554.24,831.54 v1(-1554.24,1043.36) ; v1@-1468,1043 -1326,1043 U1.8@-1270.69,987.69
  Bottom Signal w7.87: v1(-1554.24,1043.36) v1(-1468,1043.36)
MCU_A12: C22.1 R29.2 U1.14 | length 577.7
  Top Signal w7.87: R29.2@-1709.59,1033.21 C22.1@-1654.62,1033.21 ; v1(-1665.14,1000.36) C22.1@-1665.14,1022.69 ; v1(-1432,945) -1430.79,945 -1419.4,933.6 -1419.4,841.59 -1393.42,815.61 -1339.76,815.61 U1.14@-1312.45,842.92
  Bottom Signal w7.87: v1@-1663,1001 -1666,998 -1666,996 -1613.33,943.33 v1@-1432,943.33
MCU_A14/A15: C13.1 R30.2 U1.7 | length 577.5
  Top Signal w7.87: R30.2@-1709.59,949.88 C13.1@-1654.62,949.88 -1654.62,960.38 -1631.95,983.05 -1586.67,983.05 -1572.94,996.77 v1(-1572.94,1066.83) ; v1@-1481,1066.83 -1321.99,1066.83 U1.7@-1256.77,1001.6
  Bottom Signal w7.87: v1(-1572.94,1066.83) -1572.36,1067.41 -1480.04,1067.41 v1(-1479.46,1068)
MCU_A16/PGA1_INP2: C14.1 R33.2 U1.2 | length 927.8
  Top Signal w7.87: R33.2@-1709.59,699.88 C14.1@-1654.62,699.88 -1631.5,723 -1560.97,723 -1535.27,748.69 -1535.27,1089.37 -1490.64,1134 -1249.97,1134 U1.2@-1187.17,1071.2
MCU_A21/PGA1_INP3/A6: C23.1 R32.2 U1.4 | length 966.5
  Top Signal w7.87: R32.2@-1709.59,616.54 C23.1@-1654.62,616.54 -1626.16,645 -1554.28,645 -1518.28,681.01 -1518.28,1080.72 -1482,1117 -1288.65,1117 U1.4@-1215.01,1043.36
MCU_RXD: J101.2 U9.9 | length 367.3
  Top Signal w7.87: U9.9@-867.32,1648.69 -730.81,1648.69 -671.67,1707.83 J101.2@-671.67,1855
MCU_TCK: J101.8 U1.28 | length 1363.3
  Top Signal w7.87: v1@-1100.5,776.48 -1087.32,776.48 U1.28@-1056.33,745.49 ; J101.8@-971.67,1855 -936,1819.33 -936,1732.53 v1(-942.53,1726)
  Bottom Signal w7.87: v1@-1097.44,778.93 -1276.8,958.29 -1276.8,1150.2 -942.53,1484.47 v1(-942.53,1726)
  other v1: -1098.5,777.86
MCU_TDI: J101.12 U9.2 | length 348.3
  Top Signal w7.87: J101.12@-1171.67,1855 -1171.67,1839.05 -1140.61,1808 -1075,1808 -1003.43,1736.43 -1003.43,1657.61 -1012.36,1648.69 U9.2@-1042.51,1648.69
MCU_TDO: J101.10 U9.4 | length 332.3
  Top Signal w7.87: J101.10@-1071.67,1855 -1071.67,1835.67 -985,1749 -985,1621 -996.68,1609.32 U9.4@-1042.51,1609.32
MCU_TMS: J101.6 R31.1 U1.30 | length 1407.8
  Top Signal w7.87: v1(-1057.5,804.86) -1057.5,802.34 U1.30@-1028.49,773.33 ; v1@-916,1725 -916,1818 -879,1855 J101.6@-871.67,1855
  Bottom Signal w5.91: R31.1@-1028.75,776.11 R31.1@-1025.71,776.11
  Bottom Signal w7.87: R31.1@-1028.75,776.11 v1(-1057.5,804.86) -1059.06,803.3 -1095.3,803.3 -1256.22,964.22 -1256.22,1143.78 -926,1474 -926,1714.53 v1(-915.53,1725)
MCU_TXD: J101.4 U9.7 | length 387
  Top Signal w7.87: U9.7@-867.32,1609.32 -894.32,1609.32 -910,1625 -910,1670.2 -887.88,1692.32 -801.68,1692.32 -771.67,1722.33 J101.4@-771.67,1855
NetC1_2: C1.2 J4/J2.39 R2.2 | length 174
  Top Signal w7.87: C1.2@-476.84,1431 -452,1431 -444.38,1423.38 R2.2@-444.38,1381 -354,1381 J4/J2.39@-350,1385
NetC2_2: C2.2 J4/J2.40 R1.2 | length 168.4
  Top Signal w7.87: C2.2@-476.84,1530.25 -460.25,1530.25 -444.38,1514.38 R1.2@-444.38,1481 -440.38,1485 J4/J2.40@-350,1485
NetC57_2: C57.2 U12.3 U12.4 U12.5 | length 348.3
  Top Signal w19.68: U12.5@-1629.49,2420 -1702.64,2420 -1717.56,2434.92 -1717.56,2470.63 ; U12.4@-1629.49,2470 -1716.93,2470 -1717.56,2470.63 ; U12.3@-1629.49,2520 -1629.49,2518.32 -1679.36,2518.32 -1692.05,2505.63 C57.2@-1717.56,2505.63 -1717.56,2470.63
NetC63_1: C63.1 U14.6 | length 47.5
  Top Signal w13.78: v1(-2006,1941) -1983.29,1941 C63.1@-1982.12,1942.17
  Bottom Signal w13.78: v1@-2005.2,1940.2 U14.6@-1982.12,1940.2
NetC65_2: C65.2 R70.2 U2.96 | length 137.4
  Top Signal w7.87: U2.96@-296.65,2794.09 -239.92,2794.09 C65.2@-232.8,2801.22 -232.8,2843.66 -222.99,2853.46 R70.2@-208.7,2853.46
NetC74_1: C74.1 C75.2 C76.1 U2.87 U2.115 | length 727.5
  Top Signal w10: v1(-639.17,2814.49) U2.115@-639.17,2853.15 ; v1(-334.72,2651.77) U2.87@-296.06,2651.77
  Bottom Signal w10: -682.36,2794.57 -682.32,2794.61 ; C75.2@-643.15,2794.61 C75.2@-639.17,2798.58 ; C74.1@-359.96,2653.9 C74.1@-357.83,2651.77
  Bottom Signal w11.81: C76.1@-699.13,2796.06 C75.2@-643.15,2796.06 ; C75.2@-639.17,2798.58 v1(-639.17,2814.49) ; C74.1@-357.83,2651.77 v1(-334.72,2651.77)
  Bottom Signal w19.68: C76.1@-699.17,2796.02 -699.17,2810.55 -659.72,2850 -392.48,2850 -360.98,2818.5 C74.1@-360.98,2654.09
NetC77_2: C77.2 R77.1 U2.68 | length 223.5
  Top Signal w7.87: U2.68@-296.65,2353.15 -260.98,2353.15 -235.87,2328.03 -235.87,2244.02 -223.82,2231.97 R77.1@-206.34,2231.97
  Bottom Signal w11.81: C77.2@-285.47,2349.72 -257.76,2349.72 v1(-253.5,2345.47)
NetC78_1: C78.1 U2.89 Y2.3 | length 144.7
  Top Signal w7.87: U2.89@-296.65,2683.86 -221.06,2683.86 C78.1@-205.98,2698.94 ; C78.1@-201.98,2699 -157.34,2699 Y2.3@-155.12,2701.22
NetC79_1: C79.1 U2.88 Y2.1 | length 250.5
  Top Signal w7.87: U2.88@-296.65,2668.11 -236.85,2668.11 -205.98,2637.24 -205.98,2640.08 -188.15,2657.91 -129.53,2657.91 -88.31,2616.69 Y2.1@-88.31,2618.8
NetJ17_2: J17.2 L4.1 U23.A1 U23.C1 | length 455.7
  Bottom Signal w11.81: L4.1@-2137,1745.73 -2180.73,1745.73 -2203,1768 -2203,1858 -2183,1878 -2104,1878 -2075,1849 U23.C1@-2075,1818
  Bottom Signal w39.37: L4.1@-2137,1745.73 L4.1@-2123.27,1745.73 ; L4.1@-2122.27,1745.73 -2110.73,1745.73 J17.2@-2050,1685
NetL4_2: L4.2 U23.B1 | length 9.3
  Bottom Signal w15.75: L4.2@-2137,1825.73 L4.2@-2127.73,1825.73
NetLED0_2: LED0.2 R64.1 | length 53.6
  Top Signal w19.68: LED0.2@-1694.15,2059.39 R64.1@-1640.59,2059.39
NetLED1_2: LED1.2 R62.1 | length 54
  Top Signal w15.75: LED1.2@-1690.84,1660 R62.1@-1636.87,1660
NetLED2_2: LED2.2 R72.1 | length 57
  Top Signal w7.87: R72.1@-1015,2766.61 LED2.2@-1015,2823.66
NetLED3_2: LED3.2 R73.1 | length 57
  Top Signal w7.87: R73.1@-1100,2766.61 LED3.2@-1100,2823.66
NetLED4_1: LED4.1 U15.6 | length 832.3
  Top Signal w8: U15.6@-664.1,985.59 v1(-664.1,1197) ; v1(-562.6,1679.04) -534.34,1679.04 -506.33,1707.05 -506.33,1709.02 -488.67,1726.67 LED4.1@-486.7,1726.67
  Bottom Signal w8: v1(-664.1,1197) -664.1,1577.53 v1(-562.6,1679.04)
NetLED4_2: LED4.2 R4.1 | length 92.6
  Top Signal w8: R4.1@-565.85,1782.41 -565.85,1786.35 -542.85,1809.35 LED4.2@-486.7,1809.35
NetLED5_1: LED5.1 U15.4 | length 902.2
  Top Signal w8: U15.4@-589.3,985.59 v1(-589.3,1197) ; v1(-560.5,1647.19) -480.72,1647.19 -425.31,1702.6 LED5.1@-405.69,1722.22
  Bottom Signal w8: v1(-589.3,1197) -641,1248.7 -641,1566.69 v1(-560.5,1647.19)
NetLED5_2: LED5.2 R5.1 | length 85.8
  Top Signal w8: LED5.2@-405.69,1804.9 -353.97,1804.9 -343.23,1794.16 -339.3,1794.16 -331.49,1786.35 R5.1@-331.49,1782.41
NetLED6_2: LED6.2 R61.1 | length 58.1
  Top Signal w15.75: LED6.2@-1690.85,1752 R61.1@-1632.76,1752
NetLED7_2: LED7.2 R54.1 | length 76.2
  Top Signal w30: R54.1@-2023.31,2488.35 -2023.31,2426.54 LED7.2@-2013.15,2416.38
NetR3_1: R3.1 R8.2 U15.1 | length 129.7
  Top Signal w8: R3.1@-727.87,921.87 -727.87,862.23 -712.78,877.32 U15.1@-664.1,877.32
NetR7_1: R7.1 R9.2 U15.3 | length 178.6
  Top Signal w8: R9.2@-575.17,808.71 -589.3,822.84 U15.3@-589.3,877.32 -589.3,883.19 -581.49,891 -559,891 -531.44,918.56 R7.1@-531.44,944.29
NetR14_1: R14.1 R18.2 U6.2 | length 133.6
  Top Signal w11.81: U6.2@-496.61,127.34 v1@-461.34,127.34
  Bottom Signal w11.81: v1(-460,126) -459.8,125.8 R18.2@-423.5,125.8 R14.1@-423.5,187.5
NetR15_2: R15.2 S3.5 | length 79.8
  Top Signal w5: S3.5@-1314.7,445.09 v1(-1272.68,445.09)
  Bottom Signal w5: R15.2@-1310.42,445.09 v1(-1272.68,445.09)
NetR16_1: R16.1 S3.2 | length 81.3
  Top Signal w5: v1(-1210.85,445.09) S3.2@-1169.37,445.09
  Bottom Signal w5: v1(-1210.85,445.09) R16.1@-1171.01,445.09
NetR17_1: R17.1 R19.1 U6.22 | length 134.4
  Top Signal w11.81: v1@-765.11,152.93 U6.22@-728.89,152.93
  Bottom Signal w11.81: R17.1@-804,211 -803.83,210.83 R19.1@-803.83,151.17 -799.99,155 v1(-767.17,155)
NetR55_2: R55.2 U12.6 | length 75.8
  Top Signal w7.87: R55.2@-1704.92,2369.21 R55.2@-1704.13,2370 U12.6@-1629.49,2370
NetR56_1: R56.1 U12.11 | length 93
  Top Signal w10.63: U12.11@-1245.63,2370 -1225.75,2370 -1209.63,2353.88 -1184.7,2353.88 R56.1@-1166.73,2371.85
NetR57_2: R57.2 U12.7 | length 76.6
  Top Signal w7.87: R57.2@-1704.92,2322.87 -1702.05,2320 U12.7@-1629.49,2320
NetR58_1: R58.1 U12.10 | length 94.8
  Top Signal w10.63: U12.10@-1247.4,2322.83 -1218.66,2322.83 -1204.15,2337.34 -1184,2337.34 R58.1@-1166.02,2319.37
NetR72_2: R72.2 U2.3 | length 130
  Top Signal w7.87: R72.2@-1015,2719.37 -989.13,2719.37 -945.9,2762.6 U2.3@-902.95,2762.6
NetR73_2: R73.2 U2.4 | length 251.2
  Top Signal w7.87: R73.2@-1100,2719.37 -1100,2695.51 -1089.05,2684.57 -994.49,2684.57 -932.2,2746.85 U2.4@-902.95,2746.85
NetR74_1: R74.1 R75.2 U2.70 | length 146.6
  Top Signal w7.87: U2.70@-296.65,2384.65 -209.92,2384.65 R74.1@-205.98,2380.71 R75.2@-205.98,2435
NetR76_2: R76.2 U2.59 | length 87
  Top Signal w7.87: R76.2@-445,2164.18 -445,2192.77 -434.45,2203.32 U2.59@-434.45,2246.85
NetR94_1: R94.1 U10.4 | length 60.6
  Bottom Signal w7.87: R94.1@-561.41,1723.92 U10.4@-500.81,1723.92
NetR95_2: R95.2 U10.1 | length 89.1
  Bottom Signal w7.87: U10.1@-412.55,1798.68 R95.2@-323.5,1798.68
QEP1_SEL: S5.2 U7.9 U7.10 U7.11 | length 533.4
  Top Signal w15.75: S5.2@-1035.28,449 -923.7,449 -892.2,417.5 v3@-676.57,417.5
  Top Signal w19.68: v3(-675.5,417.5) v3@-675,418
  Bottom Signal w15.75: U7.9@-702.32,376.36 -702.32,406.68 -691.5,417.5 v3(-675.5,417.5) ; U7.10@-675.5,377.59 v3(-675.5,417.5) ; U7.11@-651.14,376.36 -651.14,407.14 -661.5,417.5 v3(-675.5,417.5)
USB_CC1: R59.2 U13.4 U13.7 USB1.A5 | length 317.1
  Top Signal w6: R59.2@-1899.62,2476.38 -1899.62,2514.4 -1890.94,2523.08 -1821.62,2523.08 -1775.47,2569.22 -1775.47,2659.22 -1794.17,2677.93 USB1.A5@-1794.17,2693.7
USB_CC2: R60.2 U13.5 U13.6 USB1.B5 | length 562.6
  Top Signal w6: R60.2@-1841.14,2480.94 -1841.14,2503.9 -1834.96,2510.08 -1816.92,2510.08 -1755.79,2571.21 v1@-1755.79,2647.09
  Top Signal w7.87: v5(-1849.84,2733.58) -1844.29,2739.13 USB1.B5@-1844.29,2764.57
  GND w7.87: v5(-1849.84,2733.58) -1878.23,2733.58 -1920.94,2690.87 -1920.94,2645.47 -1901.22,2625.75 -1779.17,2625.75 v1(-1755.73,2649.19)
USB_D_N: R55.1 U13.1 U13.10 USB1.A7 USB1.B7 | length 572.8
  Top Signal w10.63: v1(-1838.08,2571.75) -1838.08,2573.67 -1834.53,2577.22 U13.1@-1834.53,2590.04 ; v1(-1837.25,2671.26) v1@-1836.68,2671.26 ; U13.1@-1834.45,2591.5 U13.10@-1834.53,2628.72 -1834.74,2629.02 -1834.74,2670 -1836,2671.26 v1@-1836.68,2671.26 ; USB1.A7@-1834.45,2701.58 -1834.45,2673.49 v1@-1836.68,2671.26 ; USB1.B7@-1804.92,2764.57 -1804.92,2742.22 v5(-1801.5,2738.79) ; -1794.53,2353.99 -1768.04,2353.99 -1761.81,2360.21 -1761.81,2363.5 -1755.32,2370 R55.1@-1751.38,2370
  Bottom Signal w10.63: v1(-1838.08,2571.75) -1836.72,2570.39 -1836.72,2569.27 -1833.44,2566 -1833.44,2453.69 -1772.32,2392.56 -1772.32,2360.06 -1778.55,2353.84 -1794.38,2353.84 -1801.43,2360.88 v1(-1803.35,2360.88) ; v1(-1837.25,2671.26) -1834.87,2671.26 -1833.83,2670.22 -1801.5,2702.55 v5(-1801.5,2738.79)
USB_D_P: R57.1 U13.2 U13.9 USB1.A6 USB1.B6 | length 564.9
  Top Signal w7.87: -1824.61,2740.04 -1824.61,2727.53 USB1.A6@-1814.84,2717.77
  Top Signal w10.63: -1824.61,2740.04 USB1.B6@-1824.61,2764.57 ; USB1.A6@-1814.84,2717.77 -1814.76,2717.69 USB1.A6@-1814.76,2701.58 -1814.76,2662.43 -1814.88,2662.31 -1814.88,2661.9 -1814.92,2661.86 -1814.92,2636.92 -1814.84,2636.84 U13.9@-1814.84,2628.72 U13.2@-1814.84,2595.85 -1814.84,2576.91 -1812.49,2574.56 v1(-1812.49,2571.89) ; v1(-1803.35,2330.25) -1801.43,2330.25 -1794.23,2337.45 -1767.39,2337.45 -1761.16,2331.22 -1761.16,2327.93 -1754.67,2321.44 R57.1@-1750.73,2321.44
  Bottom Signal w10.63: v1(-1812.49,2571.89) -1813.84,2570.54 -1813.84,2570.16 -1816.91,2567.09 -1816.91,2460.54 -1755.78,2399.41 -1755.78,2353.21 -1771.7,2337.3 -1794.38,2337.3 -1801.43,2330.25 v1(-1803.35,2330.25)
USB_GND: C56.1 C57.1 C60.1 JP1.3 LED7.1 R53.1 R59.1 R60.1 U12.2 U12.8 U13.3@-1795.16,2595.85 U13.8@-1795.16,2628.72 USB1.1 USB1.2 USB1.3 USB1.4 USB1.A1 USB1.A12 USB1.B1 USB1.B12 | length 1423.9
  Top Signal w11.81: v1@-1981.61,2572.8 C60.1@-1948.39,2572.8 -1948.39,2664.06 -1932.87,2679.57 USB1.A12@-1932.87,2701.58 -1932.87,2733.03 -1923.03,2742.87 USB1.B1@-1923.03,2764.57 ; v1(-1980.51,2626.18) -1953.43,2626.18 R53.1@-1952.24,2625 ; C57.1@-1718.2,2544.8 C57.1@-1716,2547 ; USB1.B12@-1706.5,2764.57 -1706.5,2737.44 -1716.34,2727.6 USB1.A1@-1716.34,2701.58 v1(-1699.37,2701.58)
  Top Signal w15.75: U13.3@-1795.16,2595.85 U13.8@-1795.16,2628.72 -1795.16,2630.59 U13.8@-1794.67,2631.08 ; U13.8@-1795.16,2625.75 v1@-1795.16,2647.21 ; v1@-1794.67,2652.55 v1(-1794.29,2652.92)
  Top Signal w19.68: v1@-1951.97,2413.39 R59.1@-1899.62,2413.39 ; -1899.62,2348.7 R59.1@-1899.62,2413.39 ; R60.1@-1838.66,2413.39 -1838.37,2413.06 -1838.37,2357.54 v2(-1838.08,2357.25) ; R60.1@-1838.66,2413.39 R59.1@-1899.62,2413.39 ; -1758.27,2533.12 -1746.59,2544.8 v1(-1739.27,2544.8) C57.1@-1718.2,2544.8 ; -1749.18,2529.7 v1@-1737.51,2541.38 ; C56.1@-1717.4,2575.12 -1686.65,2575.12 v1(-1683.26,2571.73) -1681.53,2570 U12.2@-1629.49,2570
  Top Signal w30: JP1.3@-2091.97,2276.44 LED7.1@-2091.97,2418.86 ; JP1.3@-2069.27,2253.74 -1930,2253.74 -1842.05,2253.74 ; -1899.62,2284.12 -1899.62,2298.31 v2(-1898.2,2299.73) -1898.2,2347.28 -1899.62,2348.7 ; v2@-1823.31,2235 -1629.49,2235
  other v1: -1690.12,2232.91 -1557.99,2233.94 -2144.88,2239.37 -1961.14,2327.72 -2036.97,2356.42 -2251.81,2372.52 -1734.17,2404.09 -1557.48,2410.12 -1951.97,2413.9 -2140.31,2417.24 -1755.73,2427.75 -1954.25,2478.23 -2225.51,2489.06 -1767.72,2490 -1559.57,2538.58 -2147.28,2542.56 -1981.61,2572.39 -2254.13,2593.11 -2049.61,2595.39 -2100.16,2654.02 -1948.86,2653.9 -1556.42,2680.63 -1555.59,2766.61 -2254.13,2795.32 -2116.26,2953.86
  other v2: -1811.54,2238.82 -2050.16,2253.19 -2092.13,2370.08
VDDA: C36.1 C37.2 L2.2 TP3.1 U1.18 | length 330.1
  Top Signal w15.75: U1.18@-1256.77,787.25 -1226,818.02 v1(-1226,821)
  Bottom Signal w15.75: TP3.1@-1396.67,637 -1390.58,643.09 -1390.58,667.74 L2.2@-1351.6,706.72
  Bottom Signal w20: L2.2@-1351.6,706.72 -1347.13,706.72 -1316.42,737.42 ; C36.1@-1300.64,753.21 -1316.42,737.42 ; v1(-1226,821) -1226.7,821 C37.2@-1250.97,796.74 -1310.28,737.42 -1316.42,737.42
